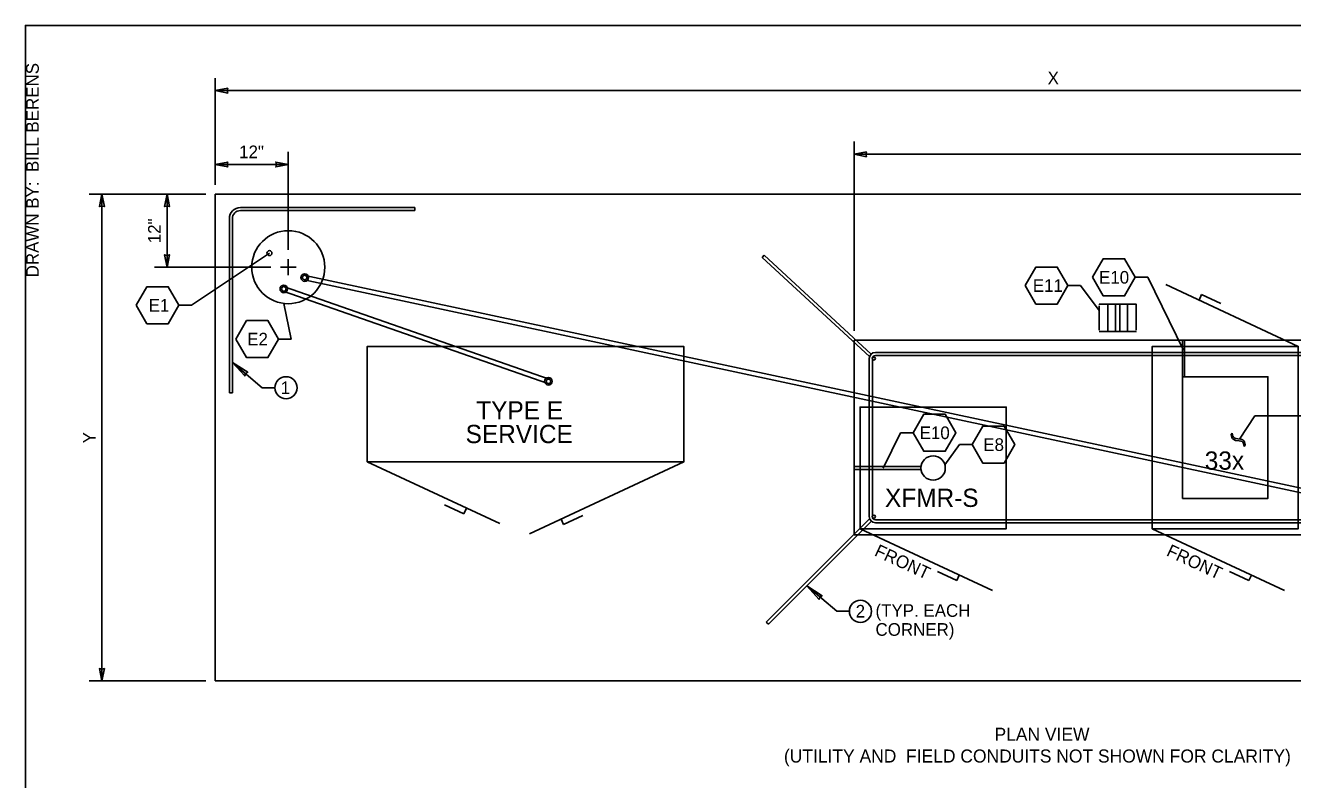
# Model space of a CAD drawing. Extents: x 99862 to 103151, y 100000 to 117076.
# Drawn here: x 99862 to 101465, y 116121 to 117076 of the extents above; entities that cross this region are included whole.
import ezdxf

# ---------------------------------------------------------------- set-up
doc = ezdxf.new("R2010")
doc.units = 0
for name, color, linetype in [('Default', 7, 'Continuous'), ('Level 1', 7, 'Continuous'), ('Level 10', 7, 'Continuous'), ('Level 11', 7, 'Continuous'), ('Level 14', 7, 'Continuous'), ('Level 15', 7, 'Continuous'), ('Level 20', 7, 'Continuous'), ('Level 3', 7, 'Continuous'), ('Level 30', 7, 'Continuous'), ('Level 6', 7, 'Continuous'), ('Level 62', 7, 'Continuous'), ('Level 7', 7, 'Continuous'), ('Level 8', 7, 'Continuous')]:
    doc.layers.add(name, color=color, linetype=linetype)

msp = doc.modelspace()

# ---------------------------------------------------------------- linework, layer by layer
at = {"layer": 'Default'}
for p, q in [((100134.1, 116845.1), (100354.5, 116845.1)), ((100354.5, 116845.1), (100354.5, 116841.3)), ((100120, 116831), (100120, 116610.7)), ((100123.9, 116831), (100123.9, 116610.7)), ((100134.1, 116841.3), (100354.5, 116841.3)), ((100793.9, 116781.9), (100796.5, 116784.7)), ((100793.9, 116781.9), (100929.7, 116656.5)), ((100796.5, 116784.7), (100931.8, 116659.8)), ((100929.3, 116654.1), (100929.3, 116454.1)), ((100933.2, 116654.1), (100933.2, 116454.1)), ((100933.2, 116653.3), (100933.8, 116652.7)), ((100934.7, 116657.2), (100936.4, 116655.5)), ((100937, 116661.8), (102010.5, 116661.8)), ((100937, 116658), (102010.5, 116658)), ((100123.9, 116610.7), (100120, 116610.7)), ((100799.1, 116320.7), (100929.7, 116451.3)), ((100801.8, 116318), (100932.6, 116448.8)), ((100932.4, 116454.1), (100933.8, 116455.4)), ((100935.5, 116451.7), (100936.5, 116452.7)), ((100937, 116450.2), (102010.5, 116450.2)), ((100937, 116446.4), (102010.5, 116446.4)), ((100799.1, 116320.7), (100801.8, 116318))]:
    msp.add_line(p, q, dxfattribs=at)
for centre in [(100935.1, 116654.1), (100935.1, 116454.1)]:
    msp.add_circle(centre, 1.92, dxfattribs=at)
for centre, radius, start, end in [((100134.1, 116831), 14.1, 90, 180), ((100134.1, 116831), 10.3, 90, 180), ((100937, 116654.1), 7.7, 90, 180), ((100937, 116654.1), 3.85, 90, 180), ((100937, 116454.1), 7.7, 180, 270), ((100937, 116454.1), 3.85, 180, 270)]:
    msp.add_arc(centre, radius, start, end, dxfattribs=at)
at = {"layer": 'Level 1'}
for p, q in [((101798, 116415.1), (100214.7, 116753.6)), ((100215.9, 116759.3), (101801, 116420.4)), ((100522.7, 116622.6), (100188, 116739.3)), ((100189.9, 116744.8), (100524.6, 116628))]:
    msp.add_line(p, q, dxfattribs=at)
msp.add_lwpolyline([(99862, 114999.5), (103151, 114999.5), (103151, 117075.5), (99862, 117075.5)], close=True, dxfattribs=at)
for centre, radius in [((100170.7, 116787.4), 3.13), ((100188.9, 116742.1), 4.81), ((100215.3, 116756.5), 4.81), ((100215.3, 116756.5), 2.89), ((100188.9, 116742.1), 2.89), ((100523.6, 116625.3), 4.81), ((100523.6, 116625.3), 2.89)]:
    msp.add_circle(centre, radius, dxfattribs=at)
at = {"layer": 'Level 10'}
for p, q in [((101240.6, 116722.7), (101240.6, 116688.1)), ((101246.3, 116722.7), (101246.3, 116688.1))]:
    msp.add_line(p, q, dxfattribs=at)
at = {"layer": 'Level 11'}
for p, q in [((100102.1, 116246.3), (100102.1, 116861.9)), ((102222.1, 116861.9), (100102.1, 116861.9)), ((100910.1, 116677.2), (102037.4, 116677.2)), ((100910.1, 116431), (100910.1, 116677.2)), ((100910.1, 116431), (102037.4, 116431)), ((102222.1, 116246.3), (100102.1, 116246.3))]:
    msp.add_line(p, q, dxfattribs=at)
msp.add_lwpolyline([(101325.6, 116631), (101433.4, 116631), (101433.4, 116477.1), (101325.6, 116477.1)], close=True, dxfattribs=at)
for centre, radius in [((100194.5, 116769.6), 46.2), ((101010.1, 116515.6), 15.4)]:
    msp.add_circle(centre, radius, dxfattribs=at)
at = {"layer": 'Level 14'}
for points in [[(101325.6, 116677.2), (101325.6, 116631)], [(101328, 116677.2), (101328, 116631)], [(100994.9, 116517.5), (100910.1, 116517.5)], [(100994.9, 116513.7), (100910.1, 116513.7)]]:
    msp.add_lwpolyline(points, dxfattribs=at)
at = {"layer": 'Level 15'}
for p, q in [((100102.1, 116873.9), (100102.1, 117008.9)), ((100102.1, 116992.9), (102222.1, 116992.9)), ((100910.1, 116689), (100910.1, 116928.4)), ((100194.5, 116791.6), (100194.5, 116915.5)), ((102037.4, 116912.4), (100910.1, 116912.4)), ((100102.1, 116899.5), (100194.5, 116899.5)), ((100090.1, 116861.9), (99942.8, 116861.9)), ((99958.8, 116246.3), (99958.8, 116861.9)), ((100041.2, 116769.6), (100041.2, 116861.9)), ((100170.7, 116787.4), (100072.2, 116721.4)), ((100194.5, 116759.6), (100194.5, 116779.6)), ((100172.5, 116769.6), (100025.2, 116769.6)), ((100184.5, 116769.6), (100204.5, 116769.6)), ((101265.8, 116756.8), (101281.8, 116756.8)), ((101281.8, 116756.8), (101326.6, 116664.7)), ((101180.6, 116746.4), (101196.6, 116746.4)), ((101219.9, 116714.8), (101196.6, 116746.4)), ((100056.2, 116721.4), (100072.2, 116721.4)), ((100189.1, 116723.7), (100198.3, 116678.6)), ((100182.3, 116678.6), (100198.3, 116678.6)), ((100123.9, 116649.2), (100161.7, 116617.1)), ((100177.7, 116617.1), (100161.7, 116617.1)), ((101397.4, 116552.3), (101417.1, 116581.7)), ((101417.1, 116581.7), (101535, 116581.7)), ((100968.8, 116560.2), (100947, 116515.4)), ((100984.8, 116560.2), (100968.8, 116560.2)), ((101388.4, 116559.7), (101387.2, 116558)), ((101387.2, 116558), (101387.4, 116556)), ((101387.4, 116556), (101387.9, 116554.3)), ((101387.9, 116554.3), (101388.8, 116552.9)), ((101388.8, 116557.4), (101388.4, 116559.7)), ((101389.3, 116555.7), (101388.8, 116557.4)), ((101390, 116554.6), (101389.3, 116555.7)), ((101391, 116553.7), (101390, 116554.6)), ((101043.3, 116545.2), (101025, 116519.7)), ((101059.3, 116545.2), (101043.3, 116545.2)), ((101388.8, 116552.9), (101390.2, 116551.7)), ((101390.2, 116551.7), (101392.7, 116550.6)), ((101392.8, 116552.9), (101391, 116553.7)), ((101392.7, 116550.6), (101397, 116550)), ((101395.3, 116552.6), (101392.8, 116552.9)), ((101399.4, 116552.1), (101395.3, 116552.6)), ((101397, 116550), (101399.4, 116549.7)), ((101401.6, 116551.1), (101399.4, 116552.1)), ((101399.4, 116549.7), (101400.8, 116549.1)), ((101400.8, 116549.1), (101401.8, 116548.1)), ((101402.9, 116550), (101401.6, 116551.1)), ((101401.8, 116548.1), (101402.6, 116546.6)), ((101402.6, 116546.6), (101403.4, 116543)), ((101403.8, 116548.6), (101402.9, 116550)), ((101403.4, 116543), (101404.6, 116544.8)), ((101404.3, 116546.9), (101403.8, 116548.6)), ((101404.6, 116544.8), (101404.3, 116546.9)), ((100850.3, 116366.5), (100888.2, 116334.4)), ((100904.2, 116334.4), (100888.2, 116334.4)), ((100090.1, 116246.3), (99942.8, 116246.3))]:
    msp.add_line(p, q, dxfattribs=at)
for points in [[(100102.1, 116992.9), (100117.9, 116989.8), (100117.1, 116992.9), (100117.9, 116996)], [(100910.1, 116912.4), (100925.8, 116909.4), (100925.1, 116912.4), (100925.8, 116915.5)], [(100102.1, 116899.5), (100117.9, 116896.4), (100117.1, 116899.5), (100117.9, 116902.6)], [(100194.5, 116899.5), (100178.7, 116896.4), (100179.5, 116899.5), (100178.7, 116902.6)], [(99958.8, 116861.9), (99955.7, 116846.2), (99958.8, 116846.9), (99961.9, 116846.2)], [(100041.2, 116861.9), (100038.1, 116846.2), (100041.2, 116846.9), (100044.2, 116846.2)], [(100041.2, 116769.6), (100044.2, 116785.3), (100041.2, 116784.5), (100038.1, 116785.3)], [(100123.9, 116649.2), (100139.4, 116632.2), (100140.5, 116635.1), (100143.2, 116636.7)], [(100850.3, 116366.5), (100865.8, 116349.5), (100866.9, 116352.5), (100869.7, 116354.1)], [(99958.8, 116246.3), (99961.9, 116262), (99958.8, 116261.3), (99955.7, 116262)]]:
    msp.add_lwpolyline(points, close=True, dxfattribs=at)
at = {"layer": 'Level 20'}
for points in [[(101211.7, 116756.8), (101225.3, 116780.2), (101252.3, 116780.2), (101265.8, 116756.8), (101252.3, 116733.3), (101225.3, 116733.3), (101211.7, 116756.8)], [(101126.5, 116746.4), (101140, 116769.8), (101167.1, 116769.8), (101180.6, 116746.4), (101167.1, 116723), (101140, 116723), (101126.5, 116746.4)], [(100002.1, 116721.4), (100015.7, 116744.9), (100042.7, 116744.9), (100056.2, 116721.4), (100042.7, 116698), (100015.7, 116698), (100002.1, 116721.4)], [(100128.2, 116678.6), (100141.8, 116702.1), (100168.8, 116702.1), (100182.3, 116678.6), (100168.8, 116655.2), (100141.8, 116655.2), (100128.2, 116678.6)], [(100984.8, 116560.2), (100998.3, 116583.6), (101025.4, 116583.6), (101038.9, 116560.2), (101025.4, 116536.8), (100998.3, 116536.8), (100984.8, 116560.2)], [(101059.3, 116545.2), (101072.8, 116568.7), (101099.9, 116568.7), (101113.4, 116545.2), (101099.9, 116521.8), (101072.8, 116521.8), (101059.3, 116545.2)]]:
    msp.add_lwpolyline(points, dxfattribs=at)
for centre in [(100191.7, 116617.1), (100918.2, 116334.4)]:
    msp.add_circle(centre, 14, dxfattribs=at)
at = {"layer": 'Level 3'}
for p, q in [((100294.5, 116523.3), (100461.9, 116445.3)), ((100694.6, 116523.3), (100499.4, 116432.3)), ((100392.3, 116469.2), (100416.7, 116457.8)), ((100416.7, 116457.8), (100419.9, 116464.8)), ((100542.8, 116444), (100539.5, 116451)), ((100567.2, 116455.4), (100542.8, 116444))]:
    msp.add_line(p, q, dxfattribs=at)
msp.add_lwpolyline([(100294.5, 116523.3), (100694.6, 116523.3), (100694.6, 116669.5), (100294.5, 116669.5)], close=True, dxfattribs=at)
at = {"layer": 'Level 30'}
for p, q in [((101219.9, 116720.8), (101219.9, 116690)), ((101231.1, 116688.1), (101231.1, 116722.7)), ((101255.8, 116688.1), (101255.8, 116722.7)), ((101267, 116720.8), (101267, 116722.7)), ((101267, 116690), (101267, 116720.8))]:
    msp.add_line(p, q, dxfattribs=at)
for points in [[(101267, 116722.7), (101267, 116722.7), (101219.9, 116722.7), (101219.9, 116722.7)], [(101219.9, 116688.1), (101267, 116688.1), (101267, 116688.1)]]:
    msp.add_lwpolyline(points, dxfattribs=at)
at = {"layer": 'Level 6'}
for p, q in [((101471.8, 116669.5), (101304.5, 116747.6)), ((101349.7, 116735), (101346.4, 116728)), ((101374.1, 116723.6), (101349.7, 116735)), ((101287.2, 116438.7), (101454.5, 116360.6)), ((101384.9, 116384.6), (101409.3, 116373.2)), ((101409.3, 116373.2), (101412.6, 116380.2))]:
    msp.add_line(p, q, dxfattribs=at)
msp.add_lwpolyline([(101287.2, 116438.7), (101471.8, 116438.7), (101471.8, 116669.5), (101287.2, 116669.5)], close=True, dxfattribs=at)
at = {"layer": 'Level 8'}
for p, q in [((100917.8, 116438.7), (101085.2, 116360.6)), ((101015.6, 116384.6), (101040, 116373.2)), ((101040, 116373.2), (101043.2, 116380.2))]:
    msp.add_line(p, q, dxfattribs=at)
msp.add_lwpolyline([(100917.8, 116438.7), (101102.5, 116438.7), (101102.5, 116592.6), (100917.8, 116592.6)], close=True, dxfattribs=at)

# ---------------------------------------------------------------- texts
at = {"layer": 'Level 20'}
for s, height, p in [('X', 16, (101154.9, 117000.9)), ('12"', 16, (100132.4, 116907.5)), ('E10', 16, (101219.9, 116748.8)), ('E11', 16, (101136.2, 116738.4)), ('E1', 16, (100017.9, 116713.4)), ('E2', 16, (100142.6, 116670.6)), ('1', 16, (100185, 116609.1)), ('E10', 16, (100993, 116552.2)), ('E8', 16, (101073.5, 116537.2)), ('2', 16, (100912.1, 116326.5)), ('(TYP. EACH', 16, (100937.2, 116327.4)), ('CORNER)', 16, (100937.2, 116303.4)), ('PLAN VIEW', 16.5, (101087.7, 116170.6)), ('(UTILITY AND  FIELD CONDUITS NOT SHOWN FOR CLARITY)', 16.5, (100821.4, 116143.1))]:
    msp.add_text(s, height=height, dxfattribs=at).set_placement(p)
for s, rotation, p in [('12"', 90, (100033.2, 116799.9)), ('Y', 90, (99950.8, 116546.8)), ('FRONT', 335, (100934.7, 116405.3)), ('FRONT', 335, (101304, 116405.3))]:
    msp.add_text(s, height=16, rotation=rotation, dxfattribs=at).set_placement(p)
at = {"layer": 'Level 6'}
msp.add_text('33x', height=23.09, dxfattribs=at).set_placement((101353.6, 116513.5))
at = {"layer": 'Level 62'}
msp.add_text('DRAWN BY:  BILL BERENS', height=16, rotation=90, dxfattribs=at).set_placement((99879, 116756.8))
at = {"layer": 'Level 7'}
for s, p in [('TYPE E', (100432.3, 116577)), ('SERVICE', (100418.8, 116547.1))]:
    msp.add_text(s, height=23.09, dxfattribs=at).set_placement(p)
at = {"layer": 'Level 8'}
msp.add_text('XFMR-S', height=23.09, dxfattribs=at).set_placement((100949.2, 116466.4))

doc.saveas('drawing.dxf')
